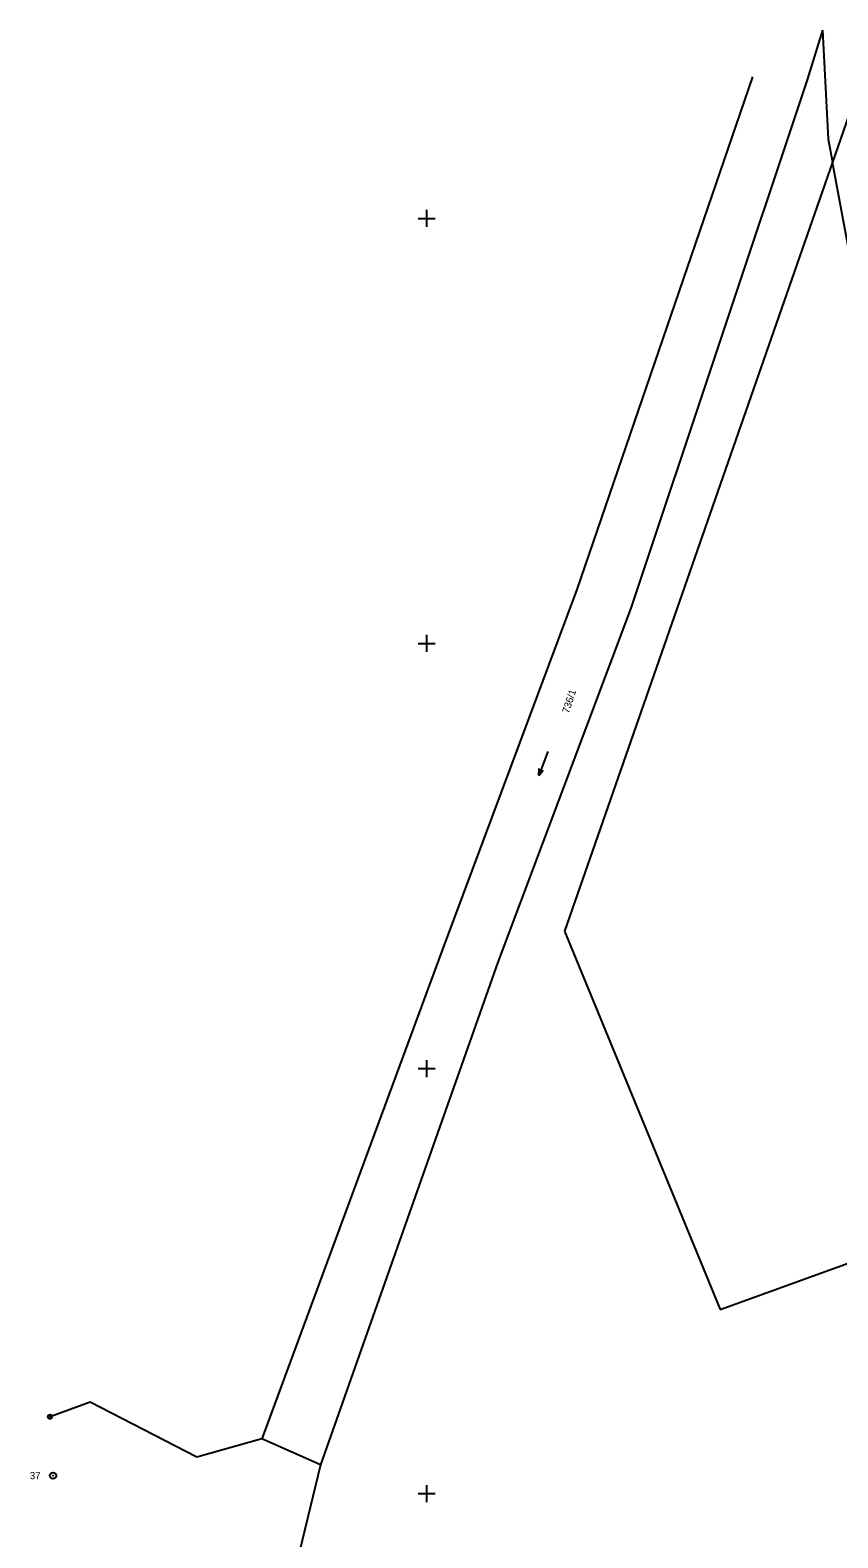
# Model space of a CAD drawing. Extents: x -493648 to -493033, y -1127718 to -1127026.
# Drawn here: x -493646.6 to -493551.6, y -1127205.2 to -1127027.9 of the extents above; entities that cross this region are included whole.
import ezdxf

# ---------------------------------------------------------------- set-up
doc = ezdxf.new("R2010")
doc.units = 0
doc.layers.add('katastrální mapa', color=7, linetype='Continuous')
doc.layers.add('síť', color=7, linetype='Continuous')

msp = doc.modelspace()

# ---------------------------------------------------------------- linework, layer by layer
at = {"layer": 'katastrální mapa'}
for p, q in [((-493553.42, -1127027.85), (-493555.23, -1127033.68)), ((-493553.42, -1127027.85), (-493552.76, -1127040.68)), ((-493561.67, -1127033.35), (-493582.33, -1127093.65)), ((-493555.23, -1127033.68), (-493575.97, -1127095.85)), ((-493550.01, -1127036.93), (-493552.26, -1127043.39)), ((-493552.76, -1127040.68), (-493552.26, -1127043.39)), ((-493552.26, -1127043.39), (-493583.77, -1127133.83)), ((-493548.19, -1127065.27), (-493552.26, -1127043.39)), ((-493582.33, -1127093.65), (-493597.95, -1127135.46)), ((-493575.97, -1127095.85), (-493591.64, -1127137.49)), ((-493585.75, -1127112.69), (-493586.79, -1127115.51)), ((-493586.79, -1127115.51), (-493586.77, -1127114.72)), ((-493586.79, -1127115.51), (-493586.3, -1127114.89)), ((-493583.77, -1127133.83), (-493565.47, -1127178.34)), ((-493597.95, -1127135.46), (-493619.38, -1127193.54)), ((-493591.64, -1127137.49), (-493612.5, -1127196.61)), ((-493565.47, -1127178.34), (-493502.87, -1127155.68)), ((-493639.59, -1127189.25), (-493644.3, -1127190.96)), ((-493627.05, -1127195.7), (-493639.59, -1127189.25)), ((-493619.38, -1127193.54), (-493627.05, -1127195.7)), ((-493612.5, -1127196.61), (-493619.38, -1127193.54)), ((-493612.5, -1127196.61), (-493616.55, -1127213.51))]:
    msp.add_line(p, q, dxfattribs=at)
for centre, radius in [((-493644.3, -1127190.96), 0.25), ((-493644.3, -1127190.96), 0.005), ((-493643.94, -1127197.89), 0.375), ((-493643.94, -1127197.89), 0.005)]:
    msp.add_circle(centre, radius, dxfattribs=at)
at = {"layer": 'síť'}
for p, q in [((-493601, -1127050), (-493599, -1127050)), ((-493600, -1127049), (-493600, -1127051)), ((-493600, -1127099), (-493600, -1127101)), ((-493601, -1127100), (-493599, -1127100)), ((-493600, -1127149), (-493600, -1127151)), ((-493601, -1127150), (-493599, -1127150)), ((-493600, -1127199), (-493600, -1127201)), ((-493601, -1127200), (-493599, -1127200))]:
    msp.add_line(p, q, dxfattribs=at)

# ---------------------------------------------------------------- texts
at = {"layer": 'katastrální mapa'}
msp.add_text('736/1', height=0.849996, rotation=71.9999972, dxfattribs=at).set_placement((-493583.27, -1127108.28))
msp.add_text('37', height=0.849996, dxfattribs=at).set_placement((-493646.68, -1127198.31))

doc.saveas('drawing.dxf')
